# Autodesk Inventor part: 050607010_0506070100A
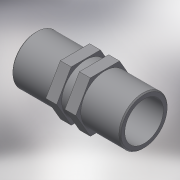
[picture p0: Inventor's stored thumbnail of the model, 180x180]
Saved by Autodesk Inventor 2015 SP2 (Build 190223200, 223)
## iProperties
Created: 2017-05
Part Number: 050607010_0506070100A
Material: Generic
Description: PLASSON NIPPLE 1"-1"
Document SubType Name: Modeling
Designer: KIM
Density: 1 g/cm^3
Appearance: Default
Author: KIM
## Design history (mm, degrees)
derived "050607.ipt"
feature "Solid1::050607.ipt"
tag "TaggingFeature1"
body "Solid1"
other parameters: "d0" = 55, "d1" = 33.249, "d2" = 36, "d3" = 26.5992, "d6" = 5.5, "d8" = 0.55, "d12" = 0, "H_" = 55, "R_" = 33.249, "E_" = 36
